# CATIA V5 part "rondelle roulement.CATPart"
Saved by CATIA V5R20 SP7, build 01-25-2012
Part number: rondelle roulement axe
Bounding box of the stored display mesh (mm): x -10.49 to -7.49, y -79.76 to -60.593, z 4.057 to 23.225
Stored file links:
  F:\Travaux\Modélisations\CFAO_2011\MMS\MMS_GR2\AA_OK\jboiteux\Catia\rondelle roulement.CATPart
  U:\finthinkmotion\stepper.CATProduct
  F:\Travaux\Modélisations\CFAO_2011\MMS\MMS_GR2\AA_OK\jboiteux\Catia\Roulement plastique.CATPart
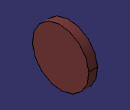
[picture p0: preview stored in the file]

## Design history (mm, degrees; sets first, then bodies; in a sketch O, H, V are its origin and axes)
Set1
  DatumSurface1: linked copy from another document
  DatumCurve1: linked copy from another document
Body1 (main body)
  Sketch1 on face of DatumSurface1, origin (-7.49, 0, 0), H (0, -1, 0), V (0, 0, 1)
    projected circle E1 centre (70.1766, 13.641) radius 9.6 from edge of DatumCurve1
  Pad1: profile Sketch1, direction (-1, 0, 0), length 3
